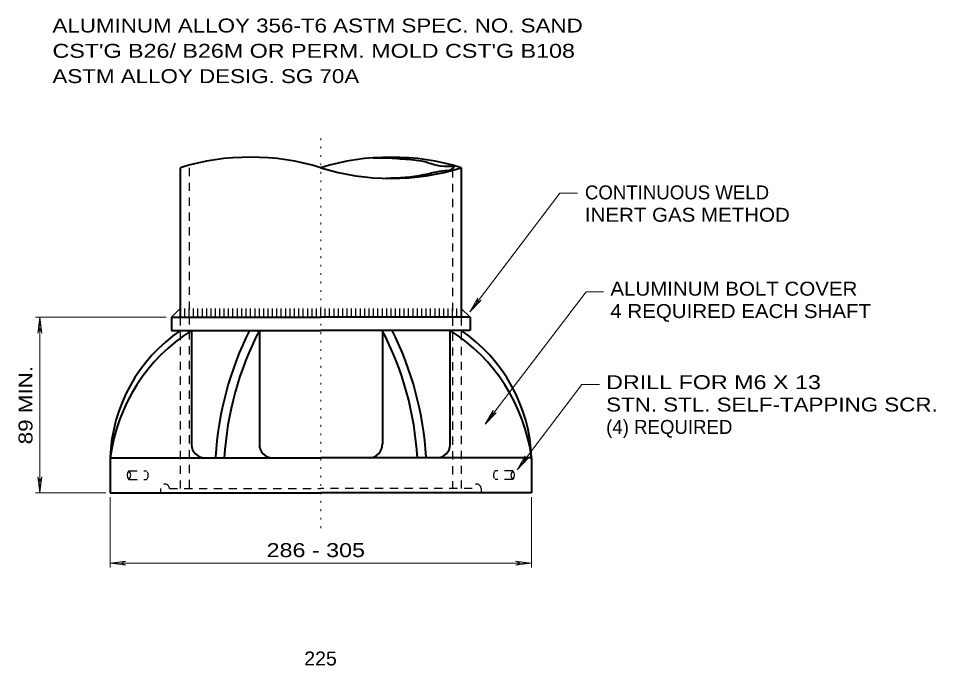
# Model space of a CAD drawing. Extents: x 312583 to 312854, y 144419 to 144597.
# Drawn here: x 312708.3 to 312758.3, y 144468.8 to 144504.1 of the extents above; entities that cross this region are included whole.
import ezdxf

# ---------------------------------------------------------------- set-up
doc = ezdxf.new("R2010")
doc.units = 0
doc.header["$LTSCALE"] = 0.3
doc.linetypes.add('DOTTED', pattern=[1.5, 0.3, -1.2])
doc.linetypes.add('SHORT_DASHED', pattern=[2.7, 1.5, -1.2])
doc.layers.add('1', color=7, linetype='Continuous', lineweight=40)
doc.layers.add('2', color=7, linetype='Continuous', lineweight=13)

msp = doc.modelspace()

# ---------------------------------------------------------------- linework, layer by layer
at = {"layer": '1'}
for p, q in [((312717.1224, 144495.9452), (312717.1224, 144487.8032)), ((312732.4557, 144495.9452), (312732.4557, 144487.8032)), ((312716.6471, 144487.8032), (312724.7891, 144487.8032)), ((312716.6471, 144487.8032), (312716.6471, 144487.0825)), ((312732.9387, 144487.8032), (312724.7891, 144487.8032)), ((312732.9387, 144487.8032), (312732.9387, 144487.0825)), ((312716.6471, 144487.0825), (312724.7891, 144487.0825)), ((312717.7434, 144480.8572), (312717.7434, 144487.0825)), ((312721.4387, 144487.0825), (312721.4387, 144480.8572)), ((312732.9387, 144487.0825), (312724.7891, 144487.0825)), ((312728.1471, 144487.0825), (312728.1471, 144480.8572)), ((312731.8424, 144480.8572), (312731.8424, 144487.0825)), ((312713.2891, 144480.1365), (312724.7891, 144480.1365)), ((312713.2891, 144480.1365), (312713.2891, 144478.2199)), ((312736.2891, 144480.1365), (312724.7891, 144480.1365)), ((312736.2891, 144480.1365), (312736.2891, 144478.2199)), ((312713.2891, 144478.2199), (312724.7891, 144478.2199)), ((312736.2891, 144478.2199), (312724.7891, 144478.2199))]:
    msp.add_line(p, q, dxfattribs=at)
at = {"layer": '1', "linetype": 'SHORT_DASHED', "lineweight": 25}
for p, q in [((312717.6054, 144495.9452), (312717.6054, 144478.4575)), ((312731.9804, 144495.8762), (312731.9804, 144478.4575)), ((312717.1224, 144487.8032), (312717.1224, 144478.4575)), ((312732.4557, 144487.8032), (312732.4557, 144478.4575)), ((312714.3164, 144479.4235), (312715.2747, 144479.4235)), ((312735.2617, 144479.4235), (312734.3034, 144479.4235)), ((312714.3164, 144478.9482), (312715.2747, 144478.9482)), ((312735.2617, 144478.9482), (312734.3034, 144478.9482)), ((312716.0491, 144478.4575), (312716.0491, 144478.2199)), ((312716.5244, 144478.4575), (312724.7891, 144478.4575)), ((312733.0537, 144478.4575), (312724.7891, 144478.4575)), ((312733.5367, 144478.4575), (312733.5367, 144478.2199))]:
    msp.add_line(p, q, dxfattribs=at)
at = {"layer": '1', "lineweight": 25}
for p, q in [((312716.6471, 144487.8032), (312717.1224, 144488.2785)), ((312717.3677, 144487.8032), (312717.3677, 144488.2785)), ((312717.6054, 144487.8032), (312717.6054, 144488.2785)), ((312717.8431, 144487.8032), (312717.8431, 144488.2785)), ((312718.0807, 144487.8032), (312718.0807, 144488.2785)), ((312718.3261, 144487.8032), (312718.3261, 144488.2785)), ((312718.5637, 144487.8032), (312718.5637, 144488.2785)), ((312718.8014, 144487.8032), (312718.8014, 144488.2785)), ((312719.0391, 144487.8032), (312719.0391, 144488.2785)), ((312719.2844, 144487.8032), (312719.2844, 144488.2785)), ((312719.5221, 144487.8032), (312719.5221, 144488.2785)), ((312719.7597, 144487.8032), (312719.7597, 144488.2785)), ((312719.9974, 144487.8032), (312719.9974, 144488.2785)), ((312720.2427, 144487.8032), (312720.2427, 144488.2785)), ((312720.4804, 144487.8032), (312720.4804, 144488.2785)), ((312720.7181, 144487.8032), (312720.7181, 144488.2785)), ((312720.9557, 144487.8032), (312720.9557, 144488.2785)), ((312721.2011, 144487.8032), (312721.2011, 144488.2785)), ((312721.4387, 144487.8032), (312721.4387, 144488.2785)), ((312721.6764, 144487.8032), (312721.6764, 144488.2785)), ((312721.9141, 144487.8032), (312721.9141, 144488.2785)), ((312722.1594, 144487.8032), (312722.1594, 144488.2785)), ((312722.3971, 144487.8032), (312722.3971, 144488.2785)), ((312722.6347, 144487.8032), (312722.6347, 144488.2785)), ((312722.8724, 144487.8032), (312722.8724, 144488.2785)), ((312723.1177, 144487.8032), (312723.1177, 144488.2785)), ((312723.3554, 144487.8032), (312723.3554, 144488.2785)), ((312723.5931, 144487.8032), (312723.5931, 144488.2785)), ((312723.8307, 144487.8032), (312723.8307, 144488.2785)), ((312724.0761, 144487.8032), (312724.0761, 144488.2785)), ((312724.3137, 144487.8032), (312724.3137, 144488.2785)), ((312724.5514, 144487.8032), (312724.5514, 144488.2785)), ((312724.7891, 144487.8032), (312724.7891, 144488.2785)), ((312724.7891, 144487.8032), (312724.7891, 144488.2785)), ((312725.0344, 144487.8032), (312725.0344, 144488.2785)), ((312725.2721, 144487.8032), (312725.2721, 144488.2785)), ((312725.5097, 144487.8032), (312725.5097, 144488.2785)), ((312725.7474, 144487.8032), (312725.7474, 144488.2785)), ((312725.9927, 144487.8032), (312725.9927, 144488.2785)), ((312726.2304, 144487.8032), (312726.2304, 144488.2785)), ((312726.4681, 144487.8032), (312726.4681, 144488.2785)), ((312726.7057, 144487.8032), (312726.7057, 144488.2785)), ((312726.9511, 144487.8032), (312726.9511, 144488.2785)), ((312727.1887, 144487.8032), (312727.1887, 144488.2785)), ((312727.4264, 144487.8032), (312727.4264, 144488.2785)), ((312727.6641, 144487.8032), (312727.6641, 144488.2785)), ((312727.9094, 144487.8032), (312727.9094, 144488.2785)), ((312728.1471, 144487.8032), (312728.1471, 144488.2785)), ((312728.3847, 144487.8032), (312728.3847, 144488.2785)), ((312728.6224, 144487.8032), (312728.6224, 144488.2785)), ((312728.8677, 144487.8032), (312728.8677, 144488.2785)), ((312729.1054, 144487.8032), (312729.1054, 144488.2785)), ((312729.3431, 144487.8032), (312729.3431, 144488.2785)), ((312729.5807, 144487.8032), (312729.5807, 144488.2785)), ((312729.8261, 144487.8032), (312729.8261, 144488.2785)), ((312730.0637, 144487.8032), (312730.0637, 144488.2785)), ((312730.3014, 144487.8032), (312730.3014, 144488.2785)), ((312730.5391, 144487.8032), (312730.5391, 144488.2785)), ((312730.7844, 144487.8032), (312730.7844, 144488.2785)), ((312731.0221, 144487.8032), (312731.0221, 144488.2785)), ((312731.2597, 144487.8032), (312731.2597, 144488.2785)), ((312731.4974, 144487.8032), (312731.4974, 144488.2785)), ((312731.7427, 144487.8032), (312731.7427, 144488.2785)), ((312731.9804, 144487.8032), (312731.9804, 144488.2785)), ((312732.2181, 144487.8032), (312732.2181, 144488.2785)), ((312732.9387, 144487.8032), (312732.4557, 144488.2785))]:
    msp.add_line(p, q, dxfattribs=at)
at = {"layer": '1'}
for centre, radius, start, end in [((312720.9576, 144483.598), 12.9304, 72.75496, 107.24505), ((312728.6243, 144483.598), 12.9304, 72.75496, 107.24505), ((312728.6243, 144508.2962), 12.9304, 252.75495, 287.24504), ((312722.0795, 144479.8104), 8.7945, 124.21849, 177.88724), ((312722.9373, 144478.8564), 9.7307, 122.28719, 172.4519), ((312736.7915, 144479.1084), 17.781, 153.35491, 176.59885), ((312736.7915, 144479.1084), 17.3018, 152.55593, 176.59975), ((312712.7905, 144479.1084), 17.3018, 3.40025, 27.44407), ((312712.7905, 144479.1084), 17.781, 3.40115, 26.64509), ((312726.6446, 144478.8564), 9.7307, 7.5481, 57.71281), ((312727.5025, 144479.8104), 8.7945, 2.11276, 55.78151), ((312718.4583, 144480.8534), 0.7188, 180, 270), ((312722.1556, 144480.8534), 0.7188, 180, 270), ((312727.4264, 144480.8534), 0.7188, 270, 0), ((312731.1237, 144480.8534), 0.7188, 270, 0)]:
    msp.add_arc(centre, radius, start, end, dxfattribs=at)
at = {"layer": '1', "lineweight": 25}
for centre, start, end in [((312714.5687, 144479.184), 136.2573, 223.7427), ((312714.068, 144479.184), 316.2573, 43.7427), ((312735.514, 144479.184), 136.2573, 223.7427), ((312735.0133, 144479.184), 316.2573, 43.7427)]:
    msp.add_arc(centre, 0.3465, start, end, dxfattribs=at)
at = {"layer": '1', "linetype": 'SHORT_DASHED', "lineweight": 25}
for centre, radius, start, end in [((312715.0263, 144479.184), 0.3465, 316.2573, 43.7427), ((312734.5557, 144479.184), 0.3465, 136.2573, 223.7427), ((312716.2867, 144478.4575), 0.2396, 0, 180), ((312733.2952, 144478.4575), 0.2396, 0, 180)]:
    msp.add_arc(centre, radius, start, end, dxfattribs=at)
at = {"layer": '1'}
msp.add_spline([(312728.3617, 144495.3855), (312730.4087, 144495.5772), (312731.5587, 144495.7995), (312732.0111, 144495.9222), (312732.0571, 144495.9682), (312731.8041, 144496.0142), (312730.3857, 144496.2902), (312729.2817, 144496.4129), (312728.0934, 144496.4819), (312727.6411, 144496.4742)], degree=3, dxfattribs=at)
at = {"layer": '2', "linetype": 'DOTTED'}
msp.add_line((312724.7891, 144476.3032), (312724.7891, 144497.6855), dxfattribs=at)
at = {"layer": '2'}
for p, q in [((312732.9234, 144488.1022), (312737.8377, 144494.5575)), ((312737.8377, 144494.5575), (312738.7961, 144494.5575)), ((312733.7514, 144481.9612), (312739.2637, 144489.1909)), ((312739.2637, 144489.1909), (312740.2221, 144489.1909)), ((312732.9234, 144488.1022), (312733.3604, 144488.8612)), ((312732.9234, 144488.1022), (312733.5367, 144488.7309)), ((312733.3604, 144488.8612), (312733.2837, 144488.5775)), ((312733.5367, 144488.7309), (312733.2837, 144488.5775)), ((312716.3481, 144487.8032), (312709.2181, 144487.8032)), ((312709.4557, 144487.8032), (312709.3484, 144486.9369)), ((312709.4557, 144478.2199), (312709.4557, 144487.8032)), ((312709.4557, 144487.8032), (312709.5631, 144486.9369)), ((312709.3484, 144486.9369), (312709.4557, 144487.2129)), ((312709.5631, 144486.9369), (312709.4557, 144487.2129)), ((312733.7514, 144481.9612), (312734.1961, 144482.7125)), ((312733.7514, 144481.9612), (312734.3647, 144482.5822)), ((312734.1961, 144482.7125), (312734.1117, 144482.4289)), ((312734.3647, 144482.5822), (312734.1117, 144482.4289)), ((312735.4994, 144479.4849), (312735.9364, 144480.2362)), ((312735.4994, 144479.4849), (312736.1051, 144480.1059)), ((312735.9364, 144480.2362), (312735.8521, 144479.9525)), ((312736.1051, 144480.1059), (312735.8521, 144479.9525)), ((312709.3484, 144479.0862), (312709.4557, 144478.8102)), ((312709.4557, 144478.2199), (312709.3484, 144479.0862)), ((312709.5631, 144479.0862), (312709.4557, 144478.8102)), ((312709.4557, 144478.2199), (312709.5631, 144479.0862)), ((312713.0514, 144478.2199), (312709.2181, 144478.2199)), ((312713.2891, 144477.9822), (312713.2891, 144474.1489)), ((312736.2891, 144477.9822), (312736.2891, 144474.1489)), ((312713.2891, 144474.3865), (312714.1554, 144474.4939)), ((312713.2891, 144474.3865), (312736.2891, 144474.3865)), ((312713.2891, 144474.3865), (312714.1554, 144474.2792)), ((312714.1554, 144474.4939), (312713.8794, 144474.3865)), ((312714.1554, 144474.2792), (312713.8794, 144474.3865)), ((312735.4227, 144474.4939), (312735.6987, 144474.3865)), ((312736.2891, 144474.3865), (312735.4227, 144474.4939)), ((312735.4227, 144474.2792), (312735.6987, 144474.3865)), ((312736.2891, 144474.3865), (312735.4227, 144474.2792))]:
    msp.add_line(p, q, dxfattribs=at)
msp.add_lwpolyline([(312735.4994, 144479.4849), (312739.0337, 144484.1309), (312739.9921, 144484.1309)], dxfattribs=at)

# ---------------------------------------------------------------- texts
for s, width, p in [('ALUMINUM ALLOY 356-T6 ASTM SPEC. NO. SAND', 1.2, (312710.1457, 144503.3272)), ("CST'G B26/ B26M OR PERM. MOLD CST'G B108", 1.25, (312710.1457, 144501.9472)), ('ASTM ALLOY DESIG. SG 70A', 1.2, (312710.1457, 144500.5672)), ('INERT GAS METHOD', 1.1, (312739.2024, 144493.0069)), ('ALUMINUM BOLT COVER', 1.1, (312740.5901, 144488.9752)), ('4 REQUIRED EACH SHAFT', 1.1, (312740.5901, 144487.7552)), ('DRILL FOR M6 X 13 ', 1.25, (312740.3601, 144483.8769)), ('STN. STL. SELF-TAPPING SCR.', 1.2, (312740.3601, 144482.6569)), ('286 - 305', 1.25, (312721.8323, 144474.718)), ('225', 1.05, (312723.8828, 144468.809))]:
    msp.add_text(s, height=0.76, dxfattribs=dict(at, width=width)).set_placement(p)
for s, p in [('CONTINUOUS WELD', (312739.2024, 144494.2269)), ('(4) REQUIRED', (312740.3601, 144481.4369))]:
    msp.add_text(s, height=0.76, dxfattribs=at).set_placement(p)
at = {"layer": '2', "width": 1.2}
msp.add_text('89 MIN.', height=0.76, rotation=90, dxfattribs=at).set_placement((312709.0551, 144480.8708))

doc.saveas('drawing.dxf')
